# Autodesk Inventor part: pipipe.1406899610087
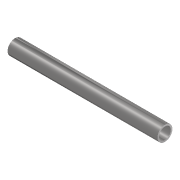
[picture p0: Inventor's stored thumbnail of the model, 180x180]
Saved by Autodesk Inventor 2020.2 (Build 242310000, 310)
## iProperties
Manager: www.cadconsulting.pl
Company: Fabian Stasiak CAD Consulting
IsCustomPart: 1
NAME: PIPING: JIS G 3458 Pipe
DATA: <meta><inlinegroups number="1" deflen="10"></inlinegroups><connections number="2"></connections><angles><a>3.14159265358979</a></angles></meta>
Created: 2014-08
Material: Stal, stopowa
Description: Rura
Document SubType Name: Modeling
Standard: JIS G 3458
Designer: F.Stasiak
Standards Organization: JIS
Language: pl-PL
Size Designation: 40 A x Sch 80 - 100
Categories: <MemberInstance><Categories><Category DisplayName="Rury cienko- i grubościenne" InternalName="4347fa0f-2144-441d-94cd-e3e15c92b736" Mnemonic="TUBEANDPIPE"><Cate
Stock Number: JIS G 3458 Rura 40 A x Sch 80
Density: 7.73 g/cm^3
Appearance: Częściowo polerowana
Catalog Web Link: www.expertbooks.pl
L: 486,000 mm
PL: 486,000 mm
Author: F.Stasiak
Subject: Zbiór ćwiczeń. Autodesk Inventor 2020. Kurs Professional
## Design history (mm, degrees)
sketch "Sketch1"
  geometry: C1 r 24.3 at (0, 0); C2 r 19.2 at (0, 0); 1 further point
  constraints: 2 centre point, 2 coincident, 1 concentric
  dimensions: "d0" = 48.6 diameter of C1 (= OD); "d1" = 38.4 diameter of C2 (= OD - 2 x t)
extrude "Extrusion1" new body sketch "Sketch1" distance "d2" = 486 (= L); taper "d3" = 0 deg
workaxis "Work Axis1"
workpoint "Work Point1"
workaxis "Work Axis2"
workpoint "Work Point2"
body "Solid1"
other parameters: "OD" = 48.6 [user parameter; used in 2 equation terms], "t" = 5.1 [user parameter; used in 1 equation term], "L" = 486 (= PL) [user parameter; used in 1 equation term], "ID" = 38.4 [user parameter], "PL" = 486 [user parameter; used in 1 equation term], "Size_Designation" = 12.345 [user parameter]
